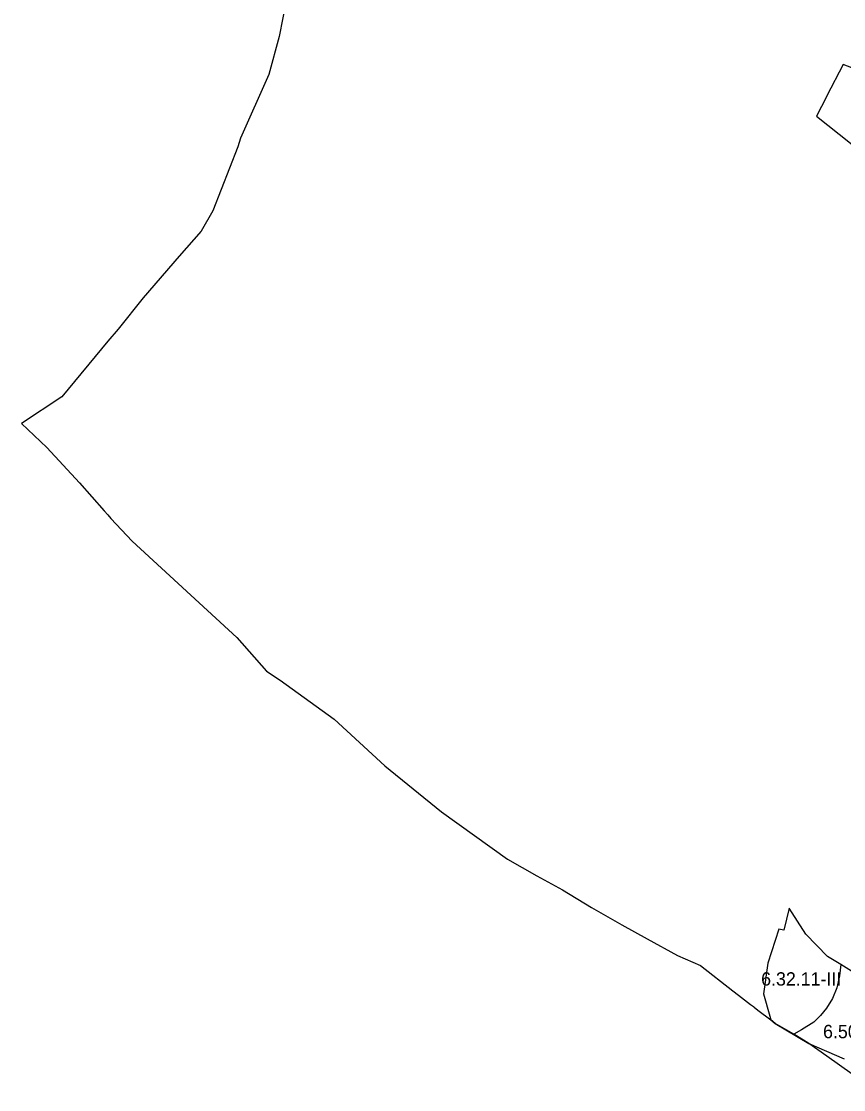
# Model space of a CAD drawing. Extents: x -555156 to -540209, y -1046851 to -1035695.
# Drawn here: x -545342 to -544725, y -1039956 to -1039153 of the extents above; entities that cross this region are included whole.
import ezdxf

# ---------------------------------------------------------------- set-up
doc = ezdxf.new("R2010")
doc.units = 0
doc.layers.add('Vrstva 27', color=7, linetype='Continuous')
doc.layers.add('Vrstva 28', color=7, linetype='Continuous')

msp = doc.modelspace()

# ---------------------------------------------------------------- linework, layer by layer
at = {"layer": 'Vrstva 28'}
for points in [[(-545143.09, -1039136.65), (-545148.62, -1039164.86), (-545156.22, -1039193.44), (-545177.52, -1039241.23), (-545179.64, -1039247.69), (-545198.34, -1039295.77), (-545207.17, -1039311.11), (-545223.69, -1039329.87), (-545250.7, -1039361.08), (-545269.38, -1039384.5), (-545277.13, -1039393.51), (-545311.83, -1039435.37), (-545342.13, -1039455.53), (-545323.06, -1039473.53), (-545298.48, -1039500.01), (-545279.94, -1039520.93), (-545277.27, -1039523.94), (-545274.85, -1039526.67), (-545258.92, -1039543.83), (-545180.39, -1039615.98), (-545158.05, -1039641.46), (-545147.67, -1039648.14), (-545107.2, -1039677.4), (-545069.18, -1039712.32), (-545026.52, -1039747.02), (-544977.08, -1039782.62), (-544954.91, -1039795.01), (-544935.69, -1039805.6), (-544913.98, -1039818.74), (-544891.25, -1039831.72), (-544872.1, -1039842.3), (-544849.29, -1039854.75), (-544832.03, -1039862.46), (-544807.73, -1039881.37), (-544803.63, -1039884.53), (-544794.47, -1039891.59), (-544792.32, -1039893.24), (-544791.9, -1039893.56), (-544789.01, -1039895.79), (-544779.31, -1039903.27), (-544775.93, -1039905.88), (-544750.69, -1039920.8), (-544724.3, -1039932.54)], [(-544649.79, -1039166.76), (-544692.27, -1039186.97), (-544681.14, -1039193.72), (-544684.72, -1039196.01), (-544689.98, -1039199.38), (-544724.88, -1039185.85), (-544737.14, -1039209.41), (-544737.49, -1039210.08), (-544745.04, -1039224.6), (-544701.14, -1039259.53), (-544697.57, -1039262.38)], [(-544765.5, -1039819.4), (-544769.65, -1039835.9), (-544773.29, -1039835.02), (-544781.66, -1039860.62), (-544784.69, -1039883.55), (-544780.12, -1039900.29), (-544779.31, -1039903.27)], [(-544726.8, -1039861.64), (-544736.64, -1039855.5), (-544752.9, -1039838.87), (-544765.5, -1039819.4)], [(-544726.8, -1039861.64), (-544727.7, -1039870.24), (-544729.65, -1039879.05), (-544733.08, -1039887.12), (-544737.56, -1039894.3), (-544741.89, -1039899.98), (-544747.12, -1039904.91), (-544756.38, -1039910.74), (-544762.14, -1039914.03)], [(-544668.11, -1039930.23), (-544675.23, -1039922.65), (-544677.32, -1039913.95), (-544678.59, -1039908.69), (-544690.61, -1039890.18), (-544704.7, -1039875.43), (-544726.8, -1039861.64)], [(-544762.14, -1039914.03), (-544775.93, -1039905.88), (-544779.31, -1039903.27)], [(-544702.25, -1039955.56), (-544707.07, -1039951.92), (-544727.65, -1039937.22), (-544737.18, -1039930.43), (-544750.69, -1039920.8), (-544762.14, -1039914.03)]]:
    msp.add_lwpolyline(points, dxfattribs=at)

# ---------------------------------------------------------------- texts
at = {"layer": 'Vrstva 27'}
for s, p in [('6.32.11-III', (-544786.576548, -1039877.43)), ('6.50.11-III', (-544740.076548, -1039916.93))]:
    msp.add_text(s, height=10, dxfattribs=at).set_placement(p)

doc.saveas('drawing.dxf')
